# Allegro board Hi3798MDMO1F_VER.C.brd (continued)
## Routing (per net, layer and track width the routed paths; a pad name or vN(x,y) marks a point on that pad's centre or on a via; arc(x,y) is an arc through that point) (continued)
ADAC_VOUTR: length 22.4
  TOP w0.203: U1.116 79.02,62.15
  TOP w0.254: C351.1 94.08,71.48 R183.1 94,70.51 89.36,70.51 88.77,69.92 84.53,69.92 79.02,64.41 79.02,62.15
AUDIO_L: length 9.1
  BOTTOM w0.254: R72.2 105.93,77.51 105.92,77.51 C339.1 105.92,82.52 107.04,83.64 J34.2
AUDIO_R: length 10.8
  BOTTOM w0.254: J34.1 95.42,83.64 95.42,83.63 97.45,83.63 98.67,82.41 98.67,77.92 ; R74.1 98.67,76.87 98.67,77.92 ; 98.67,77.92 C140.1
CORE_CTRL: length 5.3
  TOP w0.127: R23.2 86.7,58.74 85.57,58.74 84.73,57.9 U1.106
CPU_CTRL: length 3.3
  TOP w0.127: U1.107 84.7,58.3 86.15,59.75 R21.2
CVBS: length 47.1
  TOP w0.203: U1.109 81.87,62.12
  TOP w0.254: 81.87,62.12 81.87,63.78 85,66.91 108.99,66.91 112.9,70.83 112.9,76.02 113.92,77.03 R9.1 C79.1 115.68,77.89 L6.1 116.57,77.91 C80.1
CVBS_OUT: length 13.9
  TOP w0.254: L6.2 115.71,78.71 C80.2 C17.1 121.79,78.71 v2(122.3,78.2) D9.3
  BOTTOM w0.254: J34.3 123.94,79.83 v2(122.3,78.2)
DDR_ADDR0: length 101.4
  TOP w0.127: RN2.1 v2(27.69,55.32) 26.42,55.32 20.04,48.95 20.04,31.12 32.13,19.03 65.79,19.03 77.52,30.76 77.52,33.68 77.42,33.78 U1.43
  BOTTOM w0.127: RN2.1 v2(27.69,55.32)
DDR_ADDR0_A: length 19.5
  TOP w0.127: RN2.8 30.25,55.32 32.8,57.88 42.78,57.88 44.05,56.6 44.05,54.08 43.65,53.67 U3.N3
DDR_ADDR0_B: length 24.7
  TOP w0.127: U6.N3 43.65,37.37 44.05,37.77 44.05,40.09 42.67,41.47 v1(42.67,41.52)
  BOTTOM w0.127: RN11.1 29.87,55.32 42.31,42.89 42.31,41.89 v1(42.67,41.52)
DDR_ADDR1: length 63.2
  TOP w0.127: U1.27 71.02,33.3 v1(70.62,32.9) ; RN4.4 v2(27.05,39.19)
  BOTTOM w0.127: RN4.4 v2(27.05,39.19) 25.83,37.98 25.83,32.34 32.08,26.09 64.52,26.09 70.18,31.75 70.18,32.45 v1(70.62,32.9) 70.62,32.91
DDR_ADDR1_A: length 18.7
  TOP w0.127: U3.P7 42.85,50.13 42.47,49.75 42.47,49.47 42.14,49.14 41.83,49.14 41.6,48.91 41.6,48.38 41.39,48.18 39.74,48.18 30.76,39.19 RN4.5
DDR_ADDR1_B: length 18.2
  TOP w0.127: v2(38.68,31.84) 41.25,31.84 41.61,32.2 41.61,32.48 41.81,32.68 42.19,32.68 42.49,32.99 42.49,33.34 42.85,33.69 U6.P7
  BOTTOM w0.127: v2(38.68,31.84) 38.25,32.28 36.1,32.28 33.07,35.3 33.07,35.85 29.73,39.19 RN13.4
DDR_ADDR2: length 94.9
  TOP w0.127: U1.45 v1(78.22,33.66) ; R62.1 v2(27.69,48.85)
  BOTTOM w0.127: R62.1 v2(27.69,48.85) 26.65,48.85 20.47,42.67 20.47,29.39 30.4,19.46 65.58,19.46 77.37,31.24 77.37,32.8 v1(78.22,33.66)
DDR_ADDR2_A: length 15.9
  TOP w0.127: R62.2 29.97,48.85 34.71,53.58 39.55,53.58 39.93,53.2 42.5,53.2 U3.P3
DDR_ADDR2_B: length 19.6
  TOP w0.127: v1(39.17,38.93) 39.17,38.59 39.95,37.8 39.95,37.69 40.84,36.8 42.5,36.8 U6.P3
  BOTTOM w0.127: v1(39.17,38.93) 38.86,39.24 38.86,40.29 30.3,48.85 R69.2
DDR_ADDR3: length 99.7
  TOP w0.127: RN2.2 v2(27.05,54.82) 26.54,54.82 20.47,48.75 20.47,31.32 32.33,19.46 65.58,19.46 77.02,30.9 U1.42
  BOTTOM w0.127: RN2.2 v2(27.05,54.82)
DDR_ADDR3_A: length 17.8
  TOP w0.127: U3.N2 43.65,54.57 43.25,54.97 43.25,56.75 42.55,57.44 33.01,57.44 30.38,54.82 RN2.7
DDR_ADDR3_B: length 23
  TOP w0.127: v1(41.96,41.57) 43.25,40.28 43.25,38.53 43.65,38.13 U6.N2
  BOTTOM w0.127: RN11.2 29.77,54.82 41.86,42.72 41.86,41.67 v1(41.96,41.57)
DDR_ADDR4: length 60.3
  TOP w0.127: R64.1 v2(27.69,38.18) ; U1.26 v1(70.62,33.66)
  BOTTOM w0.127: R64.1 v2(27.69,38.18) 26.65,38.18 26.26,37.8 26.26,32.54 32.28,26.52 64.31,26.52 69.75,31.96 69.75,32.78 v1(70.62,33.66)
DDR_ADDR4_A: length 19
  TOP w0.127: R64.2 30.38,38.18 39.99,47.8 42.19,47.8 42.45,48.05 42.45,48.94 42.85,49.34 U3.P8
DDR_ADDR4_B: length 18
  TOP w0.127: U6.P8 42.85,32.83 42.43,32.41 42.43,31.83 42.06,31.46 38.91,31.46 38.86,31.41 38.35,31.41 v2(37.92,31.84)
  BOTTOM w0.127: v2(37.92,31.84) 35.92,31.84 32.64,35.13 32.64,35.68 30.14,38.18 R90.2
DDR_ADDR5: length 106.9
  TOP w0.127: v1(80.22,32.9) 80.62,33.3 U1.51 ; RN2.4 v2(27.05,53.8)
  BOTTOM w0.127: v1(80.22,32.9) 79.76,32.43 79.76,31.07 66.4,17.71 29.62,17.71 18.72,28.6 18.72,45.47 v2(27.05,53.8) RN2.4
DDR_ADDR5_A: length 16.3
  TOP w0.127: U3.P2 42.45,54.75 42.45,56.05 41.94,56.56 33.34,56.56 30.58,53.8 RN2.5
DDR_ADDR5_B: length 21.6
  TOP w0.127: U6.P2 42.45,38.34 42.45,39.58 41.78,40.24 v1(41.78,40.49)
  BOTTOM w0.127: v1(41.78,40.49) 41.78,40.68 41.3,41.17 41.3,42.07 29.57,53.8 RN11.4
DDR_ADDR6: length 67.3
  TOP w0.127: RN4.2 v2(27.05,40.21) 24.89,38.05 24.89,33.91 34.92,23.88 63.58,23.88 71.42,31.72 U1.28
  BOTTOM w0.127: RN4.2 v2(27.05,40.21)
DDR_ADDR6_A: length 16.6
  TOP w0.127: U3.R8 41.76,49.55 41.34,49.13 39.47,49.13 30.56,40.21 RN4.7
DDR_ADDR6_B: length 16.3
  TOP w0.127: v2(37.77,33.14) 38.19,32.72 38.85,32.72 38.91,32.78 41.38,32.78 41.73,33.14 U6.R8
  BOTTOM w0.127: v2(37.77,33.14) 37.74,33.17 36.43,33.17 34.28,35.32 34.28,35.85 29.92,40.21 RN13.2
DDR_ADDR7: length 104.1
  TOP w0.127: R61.1 v2(27.69,52.78) ; U1.50 v1(80.22,33.66)
  BOTTOM w0.127: R61.1 v2(27.69,52.78) 26.65,52.78 19.15,45.29 19.15,28.81 29.82,18.14 66.19,18.14 79.32,31.27 79.32,32.76 v1(80.22,33.66)
DDR_ADDR7_A: length 15.5
  TOP w0.127: R61.2 30.2,52.78 33.54,56.12 41.28,56.12 41.63,55.77 41.63,54.98 42.05,54.57 U3.R2
DDR_ADDR7_B: length 20.6
  TOP w0.127: v1(41.15,40.69) 41.33,40.52 41.33,40.06 41.65,39.73 41.65,38.55 42.05,38.16 U6.R2
  BOTTOM w0.127: R68.2 29.97,52.78 40.89,41.86 40.89,40.94 41.14,40.69 v1(41.15,40.69)
DDR_ADDR8: length 69
  TOP w0.127: U1.29 71.82,33.67 71.96,33.53 71.96,31.63 63.78,23.45 34.72,23.45 24.46,33.71 24.46,38.26 26.92,40.72 v2(27.69,40.72) RN4.1
  BOTTOM w0.127: RN4.1 v2(27.69,40.72)
DDR_ADDR8_A: length 15.6
  TOP w0.127: RN4.8 30.43,40.72 39.18,49.47 41.17,49.47 U3.T8
DDR_ADDR8_B: length 15.4
  TOP w0.127: U6.T8 v2(38.58,33.14)
  BOTTOM w0.127: v2(38.58,33.14) 38.12,33.6 36.61,33.6 34.71,35.49 34.71,36.03 30.02,40.72 RN13.1
DDR_ADDR9: length 91.6
  TOP w0.127: U1.37 75.02,30.83 64.97,20.78 32.92,20.78 21.79,31.91 21.79,47.91 24.77,50.88 v2(27.05,50.88) RN1.2
  BOTTOM w0.127: RN1.2 v2(27.05,50.88)
DDR_ADDR9_A: length 14.9
  TOP w0.127: U3.R3 41.85,53.55 41.48,53.92 41.12,53.92 40.39,54.65 39.9,54.65 39.7,54.85 34.12,54.85 30.15,50.88 RN1.7
DDR_ADDR9_B: length 19.7
  TOP w0.127: U6.R3 41.85,37.14 41.45,37.54 41.09,37.54 40.54,38.09 40.54,39.08 v1(40.44,39.18)
  BOTTOM w0.127: RN9.2 30.07,50.88 40.03,40.92 40.03,39.59 v1(40.44,39.18)
DDR_ADDR10: length 54
  TOP w0.127: v1(68.62,32.9) 69.02,33.3 U1.22 ; RN6.4 v2(27.05,35.26)
  BOTTOM w0.127: v1(68.62,32.9) 68.2,32.47 68.2,31.83 63.78,27.41 32.66,27.41 27.05,33.02 v2(27.05,35.26) RN6.4
DDR_ADDR10_A: length 24
  TOP w0.127: U3.L7 45.64,49.95 45.64,48.23 43.97,46.55 41.82,46.55 30.53,35.26 RN6.5
DDR_ADDR10_B: length 22.9
  TOP w0.127: U6.L7 45.25,33.94 45.64,33.55 45.64,30.9 44.17,29.43 38.53,29.43 v2(38.3,29.2)
  BOTTOM w0.127: RN8.4 29.78,35.26 30.28,34.76 30.28,34.46 35.09,29.65 37.86,29.65 v2(38.3,29.2)
DDR_ADDR11: length 71.6
  TOP w0.127: v1(72.62,32.9) 73.02,33.3 U1.32 ; RN5.3 v2(27.69,42.5)
  BOTTOM w0.127: v1(72.62,32.9) 72.14,32.41 72.14,31.8 65.1,24.77 31.47,24.77 24.46,31.78 24.46,40.67 26.29,42.5 v2(27.69,42.5) RN5.3
DDR_ADDR11_A: length 16.2
  TOP w0.127: RN5.6 30.35,42.5 38.55,50.69 41.7,50.69 U3.R7
DDR_ADDR11_B: length 16.5
  TOP w0.127: v2(37.9,34.49) 38.1,34.28 41.7,34.28 U6.R7
  BOTTOM w0.127: RN10.3 30.05,42.5 35.94,36.6 35.94,36.11 36.69,35.36 37.02,35.36 v2(37.9,34.49)
DDR_ADDR12: length 58.4
  TOP w0.127: RN6.2 v2(27.05,36.27) 26.62,36.27 26.21,35.87 26.21,34.5 35.51,25.2 62.99,25.2 69.42,31.63 69.42,34.01 U1.23
  BOTTOM w0.127: RN6.2 v2(27.05,36.27)
DDR_ADDR12_A: length 22.1
  TOP w0.127: U3.N7 44.05,49.95 44.05,48.4 44.07,48.38 44.07,48.03 43.82,47.79 43.81,47.79 43.69,47.67 43.48,47.67 42.83,47.02 41.07,47.02 30.33,36.27 RN6.7
DDR_ADDR12_B: length 20.4
  TOP w0.127: v2(37.54,30.5) 37.97,30.07 38.53,30.07 38.84,30.37 42.42,30.37 43.38,31.34 43.76,31.34 44.04,31.62 44.04,31.63 44.05,31.63 44.05,33.29 43.65,33.69 U6.N7
  BOTTOM w0.127: v2(37.54,30.5) 35.44,30.5 35.3,30.64 35.3,30.64 32.93,33 32.93,33.01 32.69,33.25 32.68,33.25 29.66,36.27 RN8.2
DDR_ADDR13: length 97.7
  TOP w0.127: U1.46 78.62,33.3 v1(78.22,32.9) ; RN1.4 v2(27.05,49.86)
  BOTTOM w0.127: v1(78.22,32.9) 77.8,32.47 77.8,31.04 65.79,19.03 30.2,19.03 20.04,29.19 20.04,42.85 v2(27.05,49.86) RN1.4
DDR_ADDR13_A: length 13.8
  TOP w0.127: RN1.5 30.35,49.86 34.51,54.02 39.68,54.02 40.15,53.55 U3.T3
DDR_ADDR13_B: length 18.2
  TOP w0.127: v1(39.8,38.55) 40.26,38.09 40.26,37.76 40.88,37.14 U6.T3
  BOTTOM w0.127: RN9.4 29.9,49.86 39.22,40.54 39.22,39.53 39.8,38.94 v1(39.8,38.55)
DDR_ADDR14: length 70
  TOP w0.127: RN5.4 v2(27.05,41.99) ; U1.31 v1(72.62,33.66)
  BOTTOM w0.127: v1(72.62,33.66) 71.7,32.74 71.7,32.01 64.9,25.2 31.67,25.2 24.89,31.98 24.89,40.49 26.39,41.99 v2(27.05,41.99) RN5.4
DDR_ADDR14_A: length 15.4
  TOP w0.127: U3.T7 38.84,50.35 30.48,41.99 RN5.5
DDR_ADDR14_B: length 15.6
  TOP w0.127: v2(37.08,34.64) 37.08,34.54 37.66,33.96 40.85,33.96 40.88,33.94 U6.T7
  BOTTOM w0.127: v2(37.08,34.64) 36.79,34.93 36.51,34.93 35.51,35.93 35.51,36.43 29.95,41.99 RN10.4
DDR_ADDR15: length 77.5
  TOP w0.127: RN5.1 v2(27.69,43.51) ; U1.36 v1(74.62,33.66)
  BOTTOM w0.127: RN5.1 v2(27.69,43.51) 25.93,43.51 23.57,41.15 23.57,29.85 29.72,23.7 65.35,23.7 74.62,32.97 v1(74.62,33.66)
DDR_ADDR15_A: length 18.6
  TOP w0.127: RN5.8 30.15,43.51 37.8,51.16 43.63,51.16 U3.M7
DDR_ADDR15_B: length 19.4
  TOP w0.127: U6.M7 43.62,34.76 38.63,34.76 v2(37.74,35.65)
  BOTTOM w0.127: v2(37.74,35.65) 37.6,35.65 36.5,36.76 36.5,37.25 30.24,43.51 RN10.1
DDR_BA0: length 106.9
  TOP w0.127: U1.47 79.02,30.97 66.19,18.14 31.72,18.14 19.15,30.71 19.15,49.33 26.42,56.59 v2(27.05,56.59) RN7.4
  BOTTOM w0.127: RN7.4 v2(27.05,56.59)
DDR_BA0_A: length 20.2
  TOP w0.127: RN7.5 30.3,56.59 32.47,58.77 43.47,58.77 44.86,57.38 44.86,54.76 U3.M2
DDR_BA0_B: length 25.5
  TOP w0.127: U6.M2 44.84,38.33 44.84,40.7 v1(43.15,42.39)
  BOTTOM w0.127: v1(43.15,42.39) 42.88,42.66 42.88,43.51 29.79,56.59 RN14.4
DDR_BA1: length 60
  TOP w0.127: RN6.1 v2(27.69,36.78) 26.52,36.78 25.78,36.05 25.78,34.29 35.31,24.77 63.18,24.77 69.95,31.54 69.95,33.6 69.82,33.73 U1.24
  BOTTOM w0.127: RN6.1 v2(27.69,36.78)
DDR_BA1_A: length 20.3
  TOP w0.127: U3.N8 43.65,49.28 43.25,48.88 43.25,47.94 42.63,47.33 42.58,47.27 40.69,47.27 30.2,36.78 RN6.8
DDR_BA1_B: length 18.6
  TOP w0.127: v2(38.3,30.5) 38.44,30.64 42.25,30.64 43.25,31.63 43.25,32.47 43.65,32.87 U6.N8
  BOTTOM w0.127: v2(38.3,30.5) 37.82,30.98 35.57,30.98 32.86,33.69 32.86,33.69 29.76,36.78 RN8.1
DDR_BA2: length 78.4
  TOP w0.127: RN3.1 v2(27.69,46.31) 26.54,46.31 23.57,43.34 23.57,33.3 34.32,22.56 64.21,22.56 73.42,31.77 U1.33
  BOTTOM w0.127: RN3.1 v2(27.69,46.31)
DDR_BA2_A: length 18.4
  TOP w0.127: U3.M3 44.45,53 43.85,52.41 35.97,52.41 29.87,46.31 RN3.8
DDR_BA2_B: length 20.3
  TOP w0.127: U6.M3 44.45,36.72 43.79,36.06 40.16,36.06 38.56,37.66 38.56,37.74 v1(38.53,37.76)
  BOTTOM w0.127: RN12.1 30.44,46.31 37.85,38.9 37.85,38.48 38.53,37.8 v1(38.53,37.76)
DDR_CASN: length 86.5
  TOP w0.127: RN3.4 v2(27.05,44.78) ; U1.40 v1(76.22,33.66)
  BOTTOM w0.127: v1(76.22,33.66) 75.36,32.8 75.36,31.17 64.97,20.78 31.01,20.78 21.79,30 21.79,40.73 25.84,44.78 v2(27.05,44.78) RN3.4
DDR_CASN_A: length 20.8
  TOP w0.127: RN3.5 30.2,44.78 37.04,51.62 44.97,51.62 45.62,52.27 45.62,53.12 U3.K3
DDR_CASN_B: length 21.9
  TOP w0.127: U6.K3 45.67,36.76 45.67,36.26 44.7,35.3 39.47,35.3 38.35,36.42 v1(38.07,36.42)
  BOTTOM w0.127: v1(38.07,36.42) 38.07,36.45 36.96,37.57 36.96,37.99 30.16,44.78 RN12.4
DDR_CKE: length 51.8
  TOP w0.127: U1.21 v1(68.62,33.66) ; R65.1 v2(27.69,34.24)
  BOTTOM w0.127: R65.1 v2(27.69,34.24) 27.69,33.02 32.87,27.84 63.58,27.84 67.77,32.03 67.77,32.8 v1(68.62,33.66) 69.11,34.15 R38.2
DDR_CKE_A: length 23.2
  TOP w0.127: R65.2 30.15,34.24 42.2,46.3 44.25,46.3 45.71,47.76 46.05,48.1 U3.K9
DDR_CKE_B: length 21.5
  TOP w0.127: U6.K9 46.05,30.75 44.35,29.05 38.81,29.05 38.51,28.75 38,28.75 v2(37.54,29.2)
  BOTTOM w0.127: v2(37.54,29.2) 34.92,29.2 29.88,34.24 R92.2
DDR_CLK0N: length 67.3
  TOP w0.152: R35.1 65.97,29.89 62.28,26.2 36.71,26.2 34.37,28.54 34.37,37.21 42.57,45.42 47.28,45.42 v1(47.41,45.56)
  TOP w0.165: U3.K7 46.05,50.64 v1(46.53,51.12)
  BOTTOM w0.152: v1(46.53,51.12) 46.76,50.89 46.76,50.64 47.22,50.18 47.22,49.37 46.65,48.8 46.65,47.63 47.4,46.88 47.4,46.44 R11.1 47.6,45.95 47.6,45.74 v1(47.41,45.56)
DDR_CLK0P: length 67.2
  TOP w0.152: R18.1 65.75,30.11 62.15,26.51 36.83,26.51 34.67,28.67 34.67,37.09 42.7,45.12 47.67,45.12 v1(48.09,45.53)
  TOP w0.165: v1(47.19,51.12) 46.85,50.78 U3.J7
  BOTTOM w0.152: v1(47.19,51.12) 47.07,51 47.07,50.77 47.52,50.31 47.52,49.24 46.95,48.67 46.95,47.76 47.7,47.01 47.7,46.45 47.84,46.31 R15.2 47.89,45.95 47.89,45.73 v1(48.09,45.53)
DDR_CLK1N: length 62.8
  TOP w0.152: v2(47.07,43.07) 46.9,42.91 46.57,42.91 45.06,44.42 43.26,44.42 35.59,36.75 35.59,29.08 37.14,27.52 61.44,27.52 63.17,29.26 R37.1
  TOP w0.165: v1(46.29,34.92) 46.05,34.68 U6.K7
  BOTTOM w0.152: v2(47.07,43.07) 47.32,42.82 47.32,42.41 46.43,41.52 46.43,37.64 45.82,37.03 45.82,35.96 R16.1 46.08,35.2 46.29,34.98 v1(46.29,34.92)
DDR_CLK1P: length 62.6
  TOP w0.152: v2(47.89,43.07) 47.75,43.07 47.28,42.6 46.44,42.6 44.93,44.11 43.38,44.11 35.89,36.62 35.89,29.2 37.26,27.83 61.32,27.83 62.96,29.47 R36.1
  TOP w0.165: U6.J7 46.85,34.68 v1(47.09,34.92)
  BOTTOM w0.152: v2(47.89,43.07) 47.62,42.81 47.62,42.28 46.74,41.4 46.74,37.51 46.13,36.9 46.13,35.98 46.58,35.53 R17.2 46.66,35.17 46.91,34.92 v1(47.09,34.92)
DDR_CSN: length 83.8
  TOP w0.127: R63.1 v2(27.69,47.45) 25.78,47.45 22.68,44.35 22.68,32.29 33.3,21.67 64.59,21.67 73.99,31.07 73.99,33.12 73.82,33.29 U1.34
  BOTTOM w0.127: R63.1 v2(27.69,47.45)
DDR_CSN_A: length 19.2
  TOP w0.127: R63.2 29.79,47.45 35.08,52.74 43.63,52.74 44.02,53.12 44.02,53.61 44.37,53.97 44.63,53.97 45.01,54.35 U3.L2
DDR_CSN_B: length 22.3
  TOP w0.127: v1(39.29,37.53) 39.29,37.36 40.31,36.34 43.53,36.34 44.04,36.85 44.04,37.36 44.17,37.48 44.58,37.48 45.03,37.94 U6.L2
  BOTTOM w0.127: v1(39.29,37.53) 39.29,37.9 38.35,38.84 38.35,39.59 30.49,47.45 R80.2
DDR_DM0: length 9.8
  TOP w0.127: U1.181 56.1,51.5 v1(56.08,51.51) ; U3.E7 v1(50.45,50.75)
  BOTTOM w0.127: v1(50.45,50.75) 50.45,51.36 51.16,52.07 51.84,52.07 52.4,51.51 v1(56.08,51.51)
DDR_DM1: length 9.2
  TOP w0.127: U3.D3 51.08,53.55 51.54,53.09 v1(52.04,53.09) ; U1.182 56.86,51.1 56.85,51.08 v1(56.82,51.08)
  BOTTOM w0.127: v1(52.04,53.09) 52.76,52.38 56.34,52.38 56.82,51.89 v1(56.82,51.08)
DDR_DM2: length 10.4
  TOP w0.127: U6.E7 v2(50.05,34.49) ; U1.215 57.22,37.9 v1(56.77,37.45)
  BOTTOM w0.127: v1(56.77,37.45) 55.63,36.31 51.88,36.31 v2(50.05,34.49)
DDR_DM3: length 8.5
  TOP w0.127: U6.D3 51.25,36.74 v1(52.05,36.74) ; U1.216 v1(57.43,37.45)
  BOTTOM w0.127: v1(52.05,36.74) 55.33,36.74 56.52,37.92 56.95,37.92 v1(57.43,37.45)
DDR_DQ0: length 11.5
  TOP w0.127: U3.E3 v1(49.65,53.95) ; U1.167 v1(56.36,57.1)
  BOTTOM w0.127: v1(56.36,57.1) 56.03,56.77 51.22,56.77 50.45,56 50.45,55.04 49.65,54.24 v1(49.65,53.95)
DDR_DQ1: length 12
  TOP w0.127: U3.F7 49.25,50.14 49.64,49.74 49.64,47.72 50.16,47.2 53.54,47.2 53.85,47.5 U1.191
DDR_DQ2: length 11.8
  TOP w0.127: U1.164 51.73,58.3 49.65,56.22 49.65,54.75 U3.F2
DDR_DQ3: length 12
  TOP w0.127: U1.192 54.01,47.1 53.72,46.81 49.98,46.81 49.06,47.74 49.05,47.74 48.81,47.97 48.81,49.12 U3.F8
DDR_DQ4: length 13.1
  TOP w0.127: v1(48.85,53.95) 48.05,53.95 U3.H3 ; U1.166 v1(56.92,57.5)
  BOTTOM w0.127: v1(48.85,53.95) 50.06,55.16 50.06,56.18 51.04,57.15 55.68,57.15 56.08,57.56 56.86,57.56 v1(56.92,57.5)
DDR_DQ5: length 14.4
  TOP w0.127: U3.H8 47.22,49.12 47.22,47.92 47.7,47.44 47.7,47.44 49.77,45.37 54.05,45.37 54.58,45.9 U1.195
DDR_DQ6: length 12.6
  TOP w0.127: U3.G2 48.84,54.75 48.84,56 51.59,58.75 U1.163
DDR_DQ7: length 14.4
  TOP w0.127: U1.194 54.45,46.3 53.89,45.75 49.93,45.75 48.05,47.62 48.05,49.79 47.65,50.2 U3.H7
DDR_DQ8: length 8
  TOP w0.127: U1.184 v1(56.94,50.3) ; v1(51.25,50.75) U3.D7
  BOTTOM w0.127: v1(51.25,50.75) 51.67,50.32 56.92,50.32 v1(56.94,50.3)
DDR_DQ9: length 9.7
  TOP w0.127: U3.C3 52.05,53.95 52.05,56.11 52.54,56.59 54.74,56.59 55.43,55.9 U1.170
DDR_DQ10: length 8.1
  TOP w0.127: U3.C8 v1(51.25,49.15) ; U1.185 v1(56.36,49.9)
  BOTTOM w0.127: v1(56.36,49.9) 52,49.9 v1(51.25,49.15)
DDR_DQ11: length 9.8
  TOP w0.127: U1.169 55.67,56.3 54.99,56.97 52.21,56.97 51.25,56.02 51.25,54.74 U3.C2
DDR_DQ12: length 5.9
  TOP w0.127: U3.A7 54.24,50.35 55.89,48.7 U1.188
DDR_DQ13: length 5.6
  TOP w0.127: U3.A2 53.89,54.35 54.64,55.1 U1.172
DDR_DQ14: length 6.9
  TOP w0.127: U1.189 55.75,48.3 54.12,49.93 53.01,49.93 52.63,49.55 U3.B8
DDR_DQ15: length 5.7
  TOP w0.127: U3.A3 53.65,53.95 54.05,53.95 54.8,54.7 U1.173
DDR_DQ16: length 13.1
  TOP w0.127: v1(56.93,43.5) U1.201 ; U6.E3 v1(49.65,37.54)
  BOTTOM w0.127: v1(56.93,43.5) 56.89,43.46 53.45,43.46 50.85,40.86 50.85,38.99 49.65,37.78 v1(49.65,37.54)
DDR_DQ17: length 20
  TOP w0.127: U6.F7 49.25,33.68 49.64,33.28 49.64,31.34 50.6,30.38 60.1,30.38 63.42,33.7 U1.8
DDR_DQ18: length 12.8
  TOP w0.127: U6.F2 49.65,38.34 49.65,39.63 53.48,43.46 54.31,43.46 55.54,44.7 U1.198
DDR_DQ19: length 20.7
  TOP w0.127: U6.F8 48.85,32.75 48.85,31.51 50.36,30 60.26,30 63.82,33.56 U1.9
DDR_DQ20: length 14.8
  TOP w0.127: U6.H3 48.05,37.54 v1(48.85,37.54) ; v1(56.39,43.9) U1.200
  BOTTOM w0.127: v1(56.39,43.9) 53.33,43.9 50.42,40.99 50.42,39.11 v1(48.85,37.54)
DDR_DQ21: length 25
  TOP w0.127: U6.H8 47.24,32.74 47.24,30.98 49.49,28.73 60.49,28.73 65.02,33.26 U1.12
DDR_DQ22: length 13.7
  TOP w0.127: U1.197 55.4,45.1 54.2,43.89 53.34,43.89 49.1,39.66 49.08,39.66 48.85,39.43 48.85,39.4 48.84,39.4 48.84,38.34 U6.G2
DDR_DQ23: length 24.4
  TOP w0.127: U1.11 64.62,33.4 60.33,29.11 49.65,29.11 48.05,30.71 48.05,33.53 U6.H7
DDR_DQ24: length 16.6
  TOP w0.127: U6.D7 50.85,33.73 51.25,33.32 51.25,31.55 51.54,31.27 60.03,31.27 62.62,33.86 U1.6
DDR_DQ25: length 10.3
  TOP w0.127: U1.204 54.58,42.3 52.05,39.78 52.05,37.55 U6.C3
DDR_DQ26: length 13.9
  TOP w0.127: U6.C8 51.65,32.87 52.04,32.48 52.04,32.11 52.43,31.73 59.95,31.73 62.22,34 U1.5
DDR_DQ27: length 10.4
  TOP w0.127: U6.C2 51.25,38.34 51.25,39.57 54.37,42.7 U1.203
DDR_DQ28: length 8.8
  TOP w0.127: U1.2 61.02,34.63 60.33,33.94 U6.A7
DDR_DQ29: length 7.8
  TOP w0.127: U1.206 55.59,41.5 54.06,39.97 54.06,38.11 53.9,37.94 U6.A2
DDR_DQ30: length 10.4
  TOP w0.127: U6.B8 52.65,33.14 53.05,33.54 60.47,33.54 61.42,34.49 U1.3
DDR_DQ31: length 8
  TOP w0.127: U6.A3 53.65,37.54 54.05,37.54 54.44,37.94 54.44,39.79 55.75,41.1 U1.207
DDR_DQS0N: length 11.6
  TOP w0.152: U1.176 57.59,53.5 57.58,53.51 55.34,53.51 53.87,52.05 49.42,52.05 48.46,53.01 48.46,53.54 U3.G3
DDR_DQS0P: length 11.5
  TOP w0.152: U1.175 57.67,53.9 57.58,53.82 55.21,53.82 53.75,52.35 49.55,52.35 48.76,53.14 48.76,53.35 48.96,53.55 U3.F3
DDR_DQS1N: length 8.1
  TOP w0.152: U3.B7 52.4,50.31 52.16,50.31 51.99,50.47 51.99,50.85 52.32,51.18 54.71,51.18 55.87,52.34 57.81,52.34 57.85,52.3 U1.179
DDR_DQS1P: length 8.2
  TOP w0.152: U3.C7 51.69,50.39 51.69,50.98 52.2,51.49 54.58,51.49 55.74,52.65 57.74,52.65 57.79,52.7 U1.178
DDR_DQS2N: length 13.7
  TOP w0.152: U1.210 57.85,39.9 57.83,39.93 57.59,39.93 57.57,39.95 57.43,39.96 56.29,39.96 55.27,38.94 55.27,37.41 53.56,35.7 49.34,35.7 48.49,36.55 48.49,36.59 48.48,36.61 48.48,37.06 48.49,37.08 48.49,37.1 U6.G3
DDR_DQS2P: length 13.5
  TOP w0.152: U6.F3 48.98,37.14 48.78,36.94 48.78,36.73 48.79,36.72 48.79,36.68 49.47,36 53.44,36 54.97,37.53 54.97,39.07 56.16,40.26 57.55,40.26 57.57,40.25 57.57,40.25 57.59,40.27 57.83,40.27 57.85,40.3 U1.209
DDR_DQS3N: length 10.1
  TOP w0.152: U1.213 57.62,38.7 57.59,38.73 56.76,38.73 56.11,38.08 56.11,36.55 54.22,34.66 52.21,34.66 51.95,34.4 51.95,34.13 52.17,33.91 52.42,33.91 U6.B7
DDR_DQS3P: length 10.2
  TOP w0.152: U1.212 57.65,39.1 57.58,39.03 56.63,39.03 55.8,38.2 55.8,36.68 54.09,34.97 52.09,34.97 51.65,34.53 U6.C7
DDR_ODT: length 108.5
  TOP w0.127: U1.48 79.42,33.73 79.53,33.63 79.53,30.84 66.4,17.71 31.52,17.71 18.72,30.51 18.72,49.53 26.29,57.1 v2(27.69,57.1) RN7.3
  BOTTOM w0.127: RN7.3 v2(27.69,57.1)
DDR_ODT_A: length 20.2
  TOP w0.127: U3.K1 45.19,56.01 45.19,57.68 43.67,59.2 32.27,59.2 30.18,57.1 RN7.6
DDR_ODT_B: length 25.6
  TOP w0.127: U6.K1 45.19,39.6 45.19,41.12 v1(43.87,42.44)
  BOTTOM w0.127: v1(43.87,42.44) 43.84,42.44 43.31,42.97 43.31,43.69 29.9,57.1 RN14.3
DDR_PLL: length 26.4
  TOP w0.203: U1.20 68.22,36.19 67.97,36.44 v2(67.97,36.47) ; v2(59.58,48.69) 59.58,48.79 59.27,49.1 U1.187
  TOP w0.381: v2(61.52,48.69) 61.52,38.78 62.13,38.16 v2(67.97,38.16)
  BOTTOM w0.305: C270.1 v2(67.97,36.47)
  BOTTOM w0.381: v2(61.52,48.69) v2(59.58,48.69) 59.47,48.58 C264.1 ; v2(67.97,36.47) v2(67.97,38.16) C11.1 LB7.1
DDR_RASN: length 113.2
  TOP w0.127: RN7.1 v2(27.69,58.12) 26.04,58.12 17.83,49.91 17.83,30.13 31.14,16.82 66.78,16.82 81.02,31.06 U1.52
  BOTTOM w0.127: RN7.1 v2(27.69,58.12)
DDR_RASN_A: length 23.2
  TOP w0.127: U3.J3 46.85,53.81 46.46,54.2 46.46,57.73 44.1,60.09 31.94,60.09 29.97,58.12 RN7.8
DDR_RASN_B: length 29
  TOP w0.127: U6.J3 46.85,37.45 46.43,37.86 46.43,41.39 44.47,43.35 v1(43.97,43.35)
  BOTTOM w0.127: v1(43.97,43.35) 43.84,43.48 43.84,44.39 30.11,58.12 RN14.1
DDR_RESETN: length 93.3
  TOP w0.127: RN1.1 v2(27.69,51.39) 24.64,51.39 21.36,48.11 21.36,31.7 32.72,20.35 65.18,20.35 75.56,30.74 75.56,33.61 75.42,33.75 U1.38
  BOTTOM w0.127: RN1.1 v2(27.69,51.39)
DDR_RESETN_A: length 15.5
  TOP w0.127: U3.T2 40.53,55.06 v1(40.06,55.06) 39.83,55.29 33.92,55.29 30.02,51.39 RN1.8
  BOTTOM w0.127: R60.2 40.26,54.86 v1(40.06,55.06) 40,55.11 C313.1
DDR_RESETN_B: length 21.6
  TOP w0.127: U6.T2 40.86,38.33 40.86,39.33 40.85,39.34 40.85,39.61 v1(40.61,39.85)
  BOTTOM w0.127: RN9.1 30.18,51.39 40.39,41.18 40.39,40.07 v1(40.61,39.85) 40.86,39.6 40.86,38.87 40.69,38.7 C314.1 41.3,38.27 R76.2
DDR_VREF_CA_A: length 4.6
  TOP w0.305: v1(44.85,49.15) U3.M8
  BOTTOM w0.381: R51.2 C207.2 43.74,50.59 R55.1 43.74,50.21 44.22,49.73 C289.1 44.39,49.15 v1(44.85,49.15)
DDR_VREF_CA_B: length 5
  TOP w0.203: v1(44.85,31.84) 44.85,32.74 U6.M8
  BOTTOM w0.381: v1(44.85,31.84) 45.06,31.63 C310.1 R107.1 45.42,30.35 R103.2 C222.2
DDR_VREF_DQ_A: length 4.4
  TOP w0.305: v1(47.68,55.92) 47.65,55.89 U3.H1
  BOTTOM w0.381: v1(47.68,55.92) 47.68,56.76 C271.1 R75.1 R54.2 C208.2
DDR_VREF_DQ_B: length 4.6
  TOP w0.305: v1(47.65,39.8) 47.65,39.8 U6.H1
  BOTTOM w0.381: R84.1 R78.2 C223.2 48.56,40.48 C308.1 47.65,40.48 47.65,39.83 47.65,39.83 v1(47.65,39.8)
DDR_WEN: length 88.1
  TOP w0.127: v1(76.22,32.9) 76.62,33.3 U1.41 ; RN3.3 v2(27.69,45.29)
  BOTTOM w0.127: RN3.3 v2(27.69,45.29) 25.53,45.29 21.36,41.13 21.36,29.8 30.81,20.35 65.18,20.35 75.79,30.97 75.79,32.47 v1(76.22,32.9)
DDR_WEN_A: length 19.9
  TOP w0.127: U3.L3 45.25,52.48 44.71,51.95 36.73,51.95 30.07,45.29 RN3.6
DDR_WEN_B: length 21.3
  TOP w0.127: U6.L3 45.25,36.37 44.45,35.58 39.7,35.58 38.14,37.14 v1(37.97,37.14)
  BOTTOM w0.127: v1(37.97,37.14) 37.97,37.19 37.39,37.77 37.39,38.17 30.26,45.29 RN12.3
FE_1V1: length 1.9
  TOP w0.203: v1(66.9,59.76) 66.9,59.77 66.62,60.04 U1.147
  BOTTOM w0.381: C248.1 66.9,60.3 v1(66.9,59.76)
FE_3V3: length 2.1
  TOP w0.203: U1.148 v1(66.22,59.74) ; U1.144 v1(67.82,59.74)
HDMI_TX0N: length 66.8
  TOP w0.152: J26.9 30.07,82.59 29.99,82.51 29.99,81.71 30.18,81.52 U24.9 ; U24.2 30.18,79.83 30.07,79.72 30.07,74.85 32.61,72.31 38.12,72.31 45.03,65.4 57.1,65.4 61.62,69.92 69.9,69.92 74.57,65.25 74.57,62.22 74.93,61.87 74.93,61.72 75.02,61.63 U1.126
  TOP w0.165: U24.2 U24.9
HDMI_TX0P: length 66.9
  TOP w0.152: J26.7 29.07,84.64 29.07,82.83 29.68,82.22 U24.10 ; U1.127 74.62,61.74 74.27,62.1 74.27,65.12 69.77,69.61 61.75,69.61 57.23,65.09 44.91,65.09 38,72 32.49,72 29.77,74.72 29.77,79.75 29.68,79.83 U24.1
  TOP w0.165: U24.1 U24.10
HDMI_TX1N: length 67.2
  TOP w0.152: U1.130 73.42,61.48 73.36,61.54 73.36,64.71 69.39,68.68 62.08,68.68 57.58,64.17 44.56,64.17 37.64,71.09 31.47,71.09 28.4,74.16 28.4,79.65 28.51,79.76 U23.5 ; J26.6 28.57,82.69 28.37,82.49 28.37,81.65 28.51,81.52 U23.6
  TOP w0.165: U23.5 U23.6
HDMI_TX1P: length 67.3
  TOP w0.152: J26.4 27.57,82.81 28.09,82.29 28.09,81.65 28.01,81.57 U23.7 ; U1.131 73.02,61.48 73.05,61.51 73.05,64.58 69.26,68.38 62.21,68.38 57.7,63.87 44.43,63.87 37.52,70.78 31.34,70.78 28.09,74.03 28.09,79.67 28.01,79.76 U23.4
  TOP w0.165: U23.4 U23.7
HDMI_TX2N: length 67.7
  TOP w0.152: U1.132 72.62,61.53 72.59,61.57 72.59,62.89 72.01,63.47 72.01,64.31 68.86,67.46 62.61,67.46 58.09,62.93 44.04,62.93 37.13,69.84 30.68,69.84 26.92,73.6 26.92,79.69 27.01,79.78 U23.2 ; U23.9 27.01,81.49 26.81,81.69 26.81,82.41 27.07,82.66 J26.3
  TOP w0.165: U23.2 U23.9
HDMI_TX2P: length 67.7
  TOP w0.152: U23.10 26.51,82.37 26.07,82.81 J26.1 ; U1.133 72.22,61.53 72.28,61.59 72.28,62.76 71.7,63.34 71.7,64.18 68.73,67.15 62.74,67.15 58.22,62.63 43.92,62.63 37.01,69.54 30.56,69.54 26.62,73.48 26.62,79.67 26.51,79.78 U23.1
  TOP w0.165: U23.1 U23.10
HDMI_TX_1V1: length 1.8
  TOP w0.203: v1(75.09,59.74) 74.53,59.74 74.22,60.04 U1.128
HDMI_TX_3V3: length 1.1
  TOP w0.203: U1.129 v1(73.82,59.74)
HDMI_TX_CEC: length 65.2
  TOP w0.127: v2(62.31,72.18) 62.38,72.18 62.53,72.03 70.79,72.03 76.73,66.09 76.73,62.09 76.22,61.58 U1.123 ; v2(45.08,68.91) 44.57,68.91 39.09,74.39 38.76,74.39 38.63,74.52 36.37,74.52 36.02,74.87 36.02,75.33 36.42,75.72 R268.2 36.42,76.3 U4.3 34.86,77.63 32.84,79.65 32.84,82.57 32.07,83.34 J26.13
  BOTTOM w0.127: v2(45.08,68.91) 45.47,69.29 56.45,69.29 57.98,70.82 59.69,70.82 61.05,72.18 v2(62.31,72.18)
HDMI_TX_HOTPLUG: length 69.8
  TOP w0.127: v2(44.07,71.07) 43.73,71.07 39.53,75.27 C149.1 R8.2 39.03,76.41 38.92,76.53 U4.4 42.01,77.63 42.36,77.98 42.36,81.69 41.33,82.72 35.69,82.72 35.07,83.34 J26.19 ; U1.119 77.82,61.6 77.49,61.93 77.49,66.4 71.08,72.81 63.53,72.81 62.74,73.6 v2(61.72,73.6)
  BOTTOM w0.127: v2(44.07,71.07) 44.45,71.07 45.47,70.06 56.13,70.06 57.66,71.58 59.18,71.58 61.2,73.6 v2(61.72,73.6)
HDMI_TX_SCL: length 63.6
  TOP w0.127: J26.15 33.07,82.94 33.2,82.81 33.2,82.21 34.57,80.84 R186.1 36.42,80.35 36.42,80.34 U4.1 37.29,79.53 37.52,79.3 37.52,76.68 38.68,75.51 38.68,74.95 38.99,74.64 39.22,74.64 44.31,69.55 v2(44.58,69.55) ; U1.122 76.62,61.53 76.98,61.89 76.98,66.19 70.87,72.31 63.02,72.31 62.69,72.64 v2(61.65,72.64)
  BOTTOM w0.127: v2(61.65,72.64) 61.13,72.64 59.56,71.07 57.87,71.07 56.35,69.55 v2(44.58,69.55)
HDMI_TX_SDA: length 69.4
  TOP w0.127: U1.121 77.02,61.52 77.24,61.74 77.24,66.3 70.98,72.56 63.27,72.56 62.74,73.09 v2(62.36,73.09) ; v2(44.2,70.31) 44.06,70.31 39.47,74.9 39.14,74.9 38.94,75.1 38.94,75.76 37.87,76.83 37.87,79.36 38.04,79.53 U4.6 39.79,79.53 40,79.74 40,80.51 40.31,80.82 R187.1 40.84,81.31 40.7,81.45 34.67,81.45 33.57,82.55 J26.16
  BOTTOM w0.127: v2(44.2,70.31) 44.7,70.31 45.21,69.8 56.24,69.8 57.76,71.33 59.44,71.33 61.2,73.09 v2(62.36,73.09)
HDMI_TXCN: length 66.1
  TOP w0.152: U1.124 75.82,61.58 75.77,61.63 75.77,65.75 70.41,71.11 61.09,71.11 56.62,66.64 45.52,66.64 38.63,73.53 33.73,73.53 31.57,75.68 31.57,79.67 31.68,79.78 U24.5 ; J26.12 31.57,82.74 31.49,82.66 31.49,81.76 31.68,81.57 U24.6
  TOP w0.165: U24.5 U24.6
HDMI_TXCP: length 66.2
  TOP w0.152: U1.125 75.42,61.58 75.46,61.62 75.46,65.63 70.28,70.81 61.21,70.81 56.74,66.34 45.39,66.34 38.51,73.22 33.6,73.22 31.27,75.56 31.27,79.65 31.18,79.73 U24.4 ; U24.7 31.18,82.25 30.57,82.86 J26.10
  TOP w0.165: U24.4 U24.7
IR_IN: length 65.9
  TOP w0.127: J3.3 121.88,16.17 123.06,17.35 123.57,17.35 123.93,17.71 R140.1 123.51,18.3 121.93,19.88 121.93,22.16 120.65,23.45 v1(117.86,23.45) ; v2(109.35,23.45) 109.35,23.39 106.31,20.35 97.65,20.35 92.43,25.57 92.43,35 91.6,35.83 86.8,35.83 85.85,36.78 85.85,38.12 85.27,38.7 U1.58
  TOP w0.254: D3.1 122.54,13.76 121.88,14.42 J3.3
  BOTTOM w0.127: v1(117.86,23.45) v2(109.35,23.45)
LED0_BASE: length 36.7
  TOP w0.127: v1(61.23,61.91) 61.41,61.73 64.83,61.73 65.02,61.54 U1.151 ; v2(45.68,68.18) 45.68,69.46 44.7,70.44 44.7,77.03 44.56,77.18 R26.2 R67.2
  BOTTOM w0.127: v2(45.68,68.18) 45.68,65.74 51.33,60.09 59.4,60.09 61.22,61.91 v1(61.23,61.91)
LED0_LINK_ACT: length 20.6
  TOP w0.127: U1.150 65.42,61.49 64.94,61.98 61.82,61.98 61.64,62.16 61.64,62.89 63.85,65.1 v2(63.85,65.15) ; R79.2 R30.2 59.33,72.63 59.06,72.36 59.06,70.82 v2(58.29,70.06)
  BOTTOM w0.127: v2(63.85,65.15) 63.13,65.86 62.48,65.86 v2(58.29,70.06)
LED_CTRL: length 36.6
  TOP w0.127: U1.57 85.31,38.3 85.6,38.02 85.6,36.65 86.67,35.58 91.49,35.58 92.15,34.92 92.15,25.44 97.69,19.91 v2(103.17,19.91)
  BOTTOM w0.127: v2(103.17,19.91) R77.1 R3.1 R31.2
LED_GREEN: length 9.1
  TOP w0.254: R34.2 117.51,19.03 Q2.3 117.84,14.77 J3.1 117.88,14.42 118.36,13.94 118.83,13.94 119.87,12.9 LED1.3
LED_RED: length 36.3
  TOP w0.254: LED1.1 114.79,12.37 115.91,11.24 121.28,11.24 ; R22.1 122.58,17.76 120.9,16.08 120.9,13.66 121.28,13.28 121.28,11.24 ; J3.5 126.32,14.29 126.32,11.96 125.6,11.24 121.28,11.24
  BOTTOM w0.254: Q1.3 107.14,20.88 R2.2 109.43,20.13 112.05,17.51 112.05,15.25 LED1.1
NF_ALE_EMMC_PWREN: length 19.7
  TOP w0.127: U1.80 84.9,47.5 85.04,47.36 91.03,47.36 92.66,48.99 101.42,48.99 101.76,48.65 U19.17
NF_CLE: length 20.3
  TOP w0.127: U19.16 102.26,48.66 101.59,49.33 92.5,49.33 90.89,47.72 85.09,47.72 84.91,47.9 U1.81
NF_CSN0_EMMC_CMD: length 35.8
  TOP w0.127: U1.82 84.89,48.3 85.16,48.03 90.74,48.03 92.34,49.63 104.61,49.63 105.76,48.49 U19.9 105.76,46.78 105.51,46.53 v2(105.51,46.51)
  TOP w0.254: U22.W5 105.26,39.91 104.97,39.62 v1(104.95,39.62)
  BOTTOM w0.127: 103.6,41.42 103.6,39.64 104.05,39.19 104.51,39.19 v1(104.95,39.62) ; 103.6,41.42 103.6,42.04 105.16,43.6 105.16,46.16 v2(105.51,46.51) ; 103.6,41.42 103.58,41.4 R212.2
NF_DQ0_EMMC_D0: length 49.3
  TOP w0.127: U22.H3 106.26,34.33 106.67,33.91 v2(106.67,33.71) ; v2(102.71,31.7) 102.13,31.7 100.26,29.83 U19.29 100.26,27.25 99.7,26.69 98.98,26.69 R189.2 97.4,26.64 97.4,29.66 97.97,30.23 97.97,43.6 95.4,46.17 86.21,46.17 86.08,46.3 U1.77
  BOTTOM w0.127: v2(102.71,31.7) 102.71,32.42 103.52,33.24 103.52,33.82 104.25,34.55 105.83,34.55 v2(106.67,33.71)
NF_DQ1_EMMC_D1: length 50.6
  TOP w0.127: U1.76 95.29,45.9 97.71,43.47 97.71,30.48 97.12,29.89 97.12,24.85 97.56,24.4 98.5,24.4 98.81,24.71 98.81,25.6 99.09,25.88 R12.2 100.76,27.19 U19.30 100.76,29.57 101.99,30.8 v2(102.74,30.8) ; v2(105.78,33.71) 105.76,33.73 U22.H4
  BOTTOM w0.127: v2(105.78,33.71) 105.32,34.17 104.38,34.17 103.87,33.66 103.87,33.13 103.25,32.5 103.25,31.31 v2(102.74,30.8)
NF_DQ2_EMMC_D2: length 50.4
  TOP w0.127: U1.75 85.01,45.5 85.15,45.64 95.18,45.64 97.46,43.35 97.46,30.74 96.86,30.14 96.86,24.57 97.42,24.01 99.76,24.01 100.08,24.33 100.08,25.6 100.36,25.88 R29.2 101.26,26.42 U19.31 101.26,29.43 102.12,30.29 103.17,30.29 v2(103.68,30.8) ; U22.H5 105.26,34.32 104.92,33.99 v2(104.92,33.68)
  BOTTOM w0.127: v2(103.68,30.8) 103.68,32.44 104.25,33.01 v2(104.92,33.68)
NF_DQ3_EMMC_D3: length 54.2
  TOP w0.089: 106.5,34.48 106.5,34.89 U22.J2
  TOP w0.127: U1.73 84.74,44.7 85.42,45.38 95.07,45.38 97.21,43.25 97.21,30.99 96.61,30.39 96.61,24.34 97.33,23.61 100.63,23.61 101.35,24.33 101.35,25.72 101.5,25.88 R58.2 101.99,25.89 101.99,26.62 101.76,26.86 U19.32 101.76,29.3 102.25,29.79 103.38,29.79 104.27,30.68 104.27,31.18 104.62,31.54 105.64,31.54 107.11,33.01 107.11,33.88 106.5,34.48
NF_DQ4_EMMC_D4: length 53.4
  TOP w0.089: 106,34.29 106,34.89 U22.J3
  TOP w0.127: v2(105.78,32.45) 105.78,32.44 106.22,32.87 106.22,33.96 106,34.17 106,34.29 ; v2(105.63,30.55) 106.26,29.92 U19.41 106.26,27.08 105.56,26.38 104.66,26.38 R176.2 103.78,25.88 103.63,25.72 103.63,24.35 102.51,23.23 97.1,23.23 95.75,24.58 95.75,43.36 94.64,44.47 84.99,44.47 84.82,44.3 U1.72
  BOTTOM w0.127: v2(105.78,32.45) 105.78,30.7 v2(105.63,30.55)
NF_DQ5_EMMC_D5: length 55.8
  TOP w0.089: U22.J4 105.5,34.89 105.5,34.34
  TOP w0.127: v2(106.52,30.55) 106.76,30.31 U19.42 106.76,27.07 105.56,25.88 R177.2 105.05,25.88 104.78,25.6 104.78,24.28 103.35,22.85 96.98,22.85 95.49,24.34 95.49,43.24 94.51,44.21 85.17,44.21 84.85,43.9 U1.71 ; 105.5,34.34 105.5,34.11 105.35,33.96 105.35,33.29 v2(104.9,32.83)
  BOTTOM w0.127: v2(106.52,30.55) 106.3,30.77 106.3,32.96 106.05,33.22 105.28,33.22 v2(104.9,32.83)
NF_DQ6_EMMC_D6: length 57.3
  TOP w0.089: U22.J5 105,34.89 105,34.47
  TOP w0.127: v2(104.89,32.01) 104.44,32.46 104.44,33.91 105,34.47 ; U1.70 84.86,43.5 85.32,43.96 94.39,43.96 95.24,43.11 95.24,24.14 96.88,22.5 104.22,22.5 106.05,24.33 106.05,25.6 106.32,25.88 R188.2 107.26,26.44 U19.43 v2(107.26,30.17)
  BOTTOM w0.127: v2(104.89,32.01) 104.89,30.59 105.38,30.1 107.19,30.1 v2(107.26,30.17)
NF_DQ7_EMMC_D7_BOOT_SEL0: length 59.9
  TOP w0.089: U22.J6 104.51,34.9 104.51,34.49 104.37,34.34
  TOP w0.127: v2(107.76,29.53) U19.44 107.76,26.91 107.96,26.7 R202.2 107.59,25.88 107.31,25.6 107.31,24.45 106.68,23.82 106.3,23.82 104.62,22.14 96.75,22.14 94.98,23.91 94.98,42.98 94.25,43.71 85.5,43.71 84.89,43.1 U1.69 ; 104.37,34.34 103.91,33.89 103.91,32.18 v2(104.13,31.97)
  BOTTOM w0.127: v2(104.13,31.97) 104.39,31.7 104.39,30.6 105.27,29.72 107.57,29.72 v2(107.76,29.53) 107.76,29.53 R33.1
NF_RDY0_EMMC_RST: length 40.4
  TOP w0.127: U1.85 84.66,49.5 85.04,49.88 90.09,49.88 91.63,51.41 105.5,51.41 106.76,50.16 U19.7 106.76,46.63 v2(107.01,46.37)
  TOP w0.254: v1(105.78,38.91) 105.55,39.15 U22.U5
  BOTTOM w0.127: v2(107.01,46.37) 109.32,44.06 109.32,39.49 108.74,38.91 R203.2 107.44,38.81 C115.1 105.89,38.81 v1(105.78,38.91)
NF_REN_EMMC_CLK: length 31.6
  TOP w0.127: v2(106.26,46.4) U19.8 106.26,49.26 104.99,50.52 91.93,50.52 90.35,48.94 R59.1
  TOP w0.254: U22.W6 104.76,40.14 104.26,39.65 v1(104.26,39.65)
  BOTTOM w0.127: v2(106.26,46.4) 105.54,45.69 105.54,43.53 103.89,41.88 103.89,40.02 v1(104.26,39.65)
NF_WEN_EMMC_DET: length 20
  TOP w0.127: U1.79 84.97,47.1 v2(85.19,46.88) 85.39,47.08 91.26,47.08 92.89,48.71 101.11,48.71 101.26,48.57 U19.18
  BOTTOM w0.127: R56.2 85.42,47.11 v2(85.19,46.88)
NF_WP: length 3.1
  TOP w0.127: v2(100.76,46.52) U19.19
  BOTTOM w0.127: v2(100.76,46.52) R89.1 R215.2
PWR_OFF/ON: length 3.4
  TOP w0.127: U1.102 86.46,56.3 R40.1 R41.1
RECOVERY: length 57.4
  TOP w0.127: S1.2 73.18,90.09 R25.2 C138.2 73.42,88.08 v2(73.41,88.09) ; v1(83.62,60.29) 83.62,63.44 v2(83.4,63.66) ; U1.103 84.88,56.7 85.04,56.86 85.04,57.6 v1(85.55,58.11) ; v2(64.26,75.64) 65.82,74.08 71.4,74.08 v2(78.93,66.55)
  BOTTOM w0.127: v2(83.4,63.66) 80.51,66.55 v2(78.93,66.55) ; v2(73.41,88.09) 66.42,88.09 64.26,85.93 v2(64.26,75.64) ; v1(85.55,58.11) 83.62,60.04 v1(83.62,60.29)
RF0: length 8.8
  TOP w0.307: U7.3 9.34,21.24 arc(9.08,19.95) 8.35,18.85 arc(8.01,18.62) C89.1 7.59,18.54 L1.2
RF1: length 3.9
  TOP w0.307: U2.7 6.44,25.2 arc(7.18,24.09) C56.1 7.43,22.78 L7.2
RFF0: length 2.3
  TOP w0.307: L1.1 4.78,18.54 C88.1 4.77,18.54 J9.1
RFF1: length 2.2
  TOP w0.307: J8.1 4.52,22.79 C50.1 L7.1
RX+_PHY0: length 21.3
  TOP w0.152: U1.143 68.22,61.6 68.28,61.65 68.28,62.16 67.79,62.64 67.79,63.27 66.95,64.11 64.87,64.11 v2(64.65,63.9)
  BOTTOM w0.152: R97.1 52.55,65.71 52.55,64.36 53.47,63.44 U8.7 U8.2 55.12,63.44 55.22,63.54 55.62,63.54 56.18,64.11 64.44,64.11 v2(64.65,63.9)
RX-_PHY0: length 21.2
  TOP w0.152: v2(64.65,64.61) 64.84,64.42 67.08,64.42 68.1,63.4 68.1,62.77 68.58,62.28 68.58,61.65 68.62,61.61 U1.142
  BOTTOM w0.152: v2(64.65,64.61) 64.46,64.42 56.06,64.42 55.49,63.85 55.22,63.85 55.12,63.95 U8.1 U8.8 53.39,63.95 52.86,64.48 52.86,65.59 52.98,65.7 R96.1
SPDIF_OUT_BOOT_SEL1: length 2.1
  TOP w0.203: v2(78.51,61.94) 78.51,61.92 78.62,61.81 U1.117
  BOTTOM w0.254: R39.1 78.26,62.2 v2(78.51,61.94)
STANDBY_PWROFF: length 228.7
  TOP w0.127: R47.1 11.78,52.61 v2(11.43,52.27) ; v2(102.92,60.27) 103.25,60.59 R73.1 ; v2(115.16,53.84) 115.16,61.23 113.91,62.48 v2(109.17,62.48) ; LB3.2 87.39,36.38 C119.1 R88.1 91.51,36.38 92.88,35.01 v2(92.88,27.03) 92.88,25.51 97.13,21.25 v2(98.32,21.25) 105.91,21.25 117.93,33.27 117.93,49.85 v2(116.55,51.24) ; v2(16.13,47.96) 16.26,47.96 16.92,47.3 16.92,28.88 29.97,15.83 67.06,15.83 73.15,21.92 79.59,21.92 82.61,18.91 96.42,18.91 v2(96.55,18.79) ; R98.1 24.1,61.9 18.67,56.47 v2(18.67,54.82)
  BOTTOM w0.127: 16.13,52.28 v2(16.13,47.96) ; 16.13,52.28 16.12,52.27 v2(11.43,52.27) ; 16.13,52.28 v2(18.67,54.82) ; v2(116.55,51.24) 116.55,52.46 v2(115.16,53.84) ; v2(102.92,60.27) 103.37,60.71 107.4,60.71 v2(109.17,62.48) ; v2(96.55,18.79) 96.55,19.47 v2(98.32,21.25) ; R5.1 v2(92.88,27.03)
TX+_PHY0: length 21.3
  TOP w0.152: U1.146 67.02,61.45 67.01,61.47 67.01,61.95 66.07,62.89 63.47,62.89 v2(63.28,62.7)
  BOTTOM w0.152: R93.1 50.66,65.7 51.18,65.18 51.18,63.71 52.35,62.54 53.17,62.54 53.28,62.43 U8.5 U8.4 55.12,62.43 55.23,62.54 56.64,62.54 57,62.89 63.09,62.89 v2(63.28,62.7)
TX-_PHY0: length 21.3
  TOP w0.152: U1.145 67.42,61.5 67.31,61.61 67.31,62.08 66.19,63.2 63.49,63.2 v2(63.28,63.41)
  BOTTOM w0.152: v2(63.28,63.41) 63.06,63.2 56.87,63.2 56.52,62.84 55.22,62.84 55.13,62.93 U8.3 U8.6 53.28,62.93 53.19,62.84 52.48,62.84 51.49,63.83 51.49,65.31 R94.1
UART0_RXD: length 35.7
  TOP w0.127: J18.2 93,20.97 91.97,21.99 87.81,21.99 R136.1 ; v2(93.55,25.52) 93.57,25.52 93.83,25.77 93.83,35.32 91.4,37.75 88.25,37.75 86.5,39.5 U1.60
  BOTTOM w0.127: J18.2 93,23.65 93.71,24.36 94.3,24.36 94.59,24.66 94.59,25.24 94.31,25.52 v2(93.55,25.52)
UART0_TXD: length 32.9
  TOP w0.127: U1.61 84.79,39.9 84.92,39.77 86.62,39.77 88.37,38.02 91.52,38.02 94.09,35.44 94.09,25.05 v2(94.03,24.99) ; R135.2 88.49,21.66 91.31,21.66 91.75,21.23 J18.3
  BOTTOM w0.127: v2(94.03,24.99) 93.75,24.99 92.58,23.82 92.58,21.91 91.75,21.07 J18.3
USB0_DM: length 29
  TOP w0.203: v2(69.58,62.7) 69.39,62.5 69.39,61.63 69.42,61.59 U1.140 ; J12.2 69.31,81.78 70.84,81.78 72.7,79.92 73.42,79.92 D5.1 73.97,79.95 74.28,79.95 74.68,79.56 74.68,77.33 73.61,76.26 73.61,75.53 C103.1 73.61,74.97 73.61,74.65 v2(73.89,74.37)
  BOTTOM w0.203: v2(69.58,62.7) 69.39,62.89 69.39,69.24 73.61,73.46 73.61,74.08 v2(73.89,74.37)
USB0_DP: length 29.1
  TOP w0.203: v2(72.99,74.37) 73.28,74.65 73.28,74.87 72.92,75.23 C106.1 73.28,75.61 73.28,76.4 74.35,77.46 74.35,79.42 74.14,79.62 74.02,79.62 D4.1 73.43,79.59 72.56,79.59 70.7,81.45 68.94,81.45 68.66,81.18 J12.3 ; v2(68.87,62.7) 69.06,62.5 69.06,61.63 69.02,61.59 U1.141
  BOTTOM w0.203: v2(68.87,62.7) 69.06,62.89 69.06,69.38 73.28,73.6 73.28,74.08 v2(72.99,74.37)
USB01_1V1: length 1.4
  TOP w0.203: v1(71.08,59.74) 70.89,59.74 70.62,60 U1.137
USB01_3V3: length 1.5
  TOP w0.203: v1(69.22,59.74) 69.55,59.74 69.82,60.01 U1.139
USB1_DM: length 84.8
  TOP w0.203: v2(8.96,40.35) 10.86,38.45 U7.7 ; U1.135 71.42,61.59 71.35,61.66 71.35,62.18 70.84,62.69 70.84,63.71 68.34,66.21 63.14,66.21 58.39,61.46 31.32,61.46 29.45,59.59 25.64,59.59 12.99,46.94 10.03,46.94 9.32,46.23 9.32,44.82 8.87,44.37 J2.4
  BOTTOM w0.203: J2.4 8.87,42.3 9.71,41.46 9.71,40.32 9.51,40.12 9.19,40.12 v2(8.96,40.35)
USB1_DP: length 84.7
  TOP w0.203: U1.136 71.02,62.04 70.51,62.55 70.51,63.57 68.2,65.88 63.28,65.88 58.53,61.13 31.46,61.13 29.59,59.26 25.78,59.26 13.13,46.61 10.17,46.61 9.65,46.09 9.65,44.82 9.83,44.65 10.72,44.65 10.87,44.49 J2.3 ; U2.2 7.36,38.95 7.96,39.55 v2(8.96,39.55)
  BOTTOM w0.203: J2.3 10.87,42.4 10.04,41.56 10.04,40.18 9.65,39.79 9.19,39.79 v2(8.96,39.55)
USB2_DM: length 112.8
  TOP w0.203: U1.89 84.95,51.1 84.98,51.14 89.8,51.14 91.06,52.39 119.53,52.39 126.75,59.61 126.75,75.63 121.92,80.46 112.01,80.46 111.02,79.47 90.3,79.47 87.3,82.47 D7.1 85.37,82.29 84.01,82.29 83.53,81.81 81.13,81.81 J7.2
USB2_DP: length 112.8
  TOP w0.203: J7.3 80.42,80.52 80.42,81.32 80.57,81.48 83.67,81.48 84.15,81.96 85.17,81.96 D6.1 85.57,81.58 86.13,82.14 87.16,82.14 90.16,79.14 111.16,79.14 112.15,80.13 121.78,80.13 126.42,75.5 126.42,59.74 119.4,52.72 90.92,52.72 89.66,51.47 84.98,51.47 84.95,51.5 U1.90
USB03_VBUS: length 22.3
  TOP w1.143: 77.57,74.62 76,76.19 76,83 75.62,83.38 ; J7.1 79.59,84.43 78.54,83.38 75.62,83.38 ; 75.62,83.38 70.64,83.38 69.59,84.43 J12.1
  vias: v2(82.42,75.13) v2(82.42,74.36) v2(83.19,75.13) v2(83.19,74.36)
USB_BOOT: length 13.3
  TOP w0.127: R42.2 86.21,65.91 84.91,64.61 84.91,59.2 84.46,58.75 U1.108
VDAC_3V3: length 1.1
  TOP w0.203: U1.112 v1(80.62,59.74)
XIN: length 11.1
  TOP w0.203: U1.63 87.38,40.7 R1.2 89.31,39.87 C364.1 89.94,39.72 90.27,40.05 90.27,40.66 90.5,40.89 92.25,40.89 93.18,39.96 X2.1
XOUT: length 5.9
  TOP w0.203: R14.1 88.95,40.61 R1.1 87.97,41.1 U1.64
$4N588: length 3.8
  TOP w0.254: R10.1 C84.1 R52.1 5.82,54.14 U15.5
$4N593: length 3.8
  TOP w0.127: U15.1 9.12,54.7 C30.1 10.73,53.77 R6.2 11.77,53.77 R47.2
$4N676: length 24.4
  TOP w0.127: R21.1 C71.1 86.62,62.89 86.82,63.09 86.82,64.76 86.99,64.94 v2(102.51,64.94) ; v2(102.51,63.34) C43.1 R7.2
  BOTTOM w0.127: v2(102.51,63.34) v2(102.51,64.94)
$4N677: length 4.7
  TOP w0.508: U11.6 108.89,59.45 R99.2 108.88,60.79 R53.1 C76.1 R70.1
$4N687: length 3
  TOP w0.508: R73.2 C8.1 104.72,59.28 U11.1
$4N714: length 4.2
  TOP w0.508: C82.1 R101.1 R13.2 89.87,23.84 R110.1 88.61,23.84 U13.6
$4N715: length 97.2
  TOP w0.127: R23.1 C72.1 89.37,64.03 113.92,64.03 116.26,61.69 116.26,54.32 v2(116.59,53.99) ; R102.2 C45.1 93.6,22.93 97.56,18.97 106.22,18.97 119.18,31.92 119.18,49.93 v2(117.73,51.38)
  BOTTOM w0.127: v2(116.59,53.99) 117.73,52.85 v2(117.73,51.38)
$4N716: length 1
  TOP w0.127: R102.1 90.69,23.19 R110.2
$4N724: length 3.9
  TOP w0.508: U13.1 88.41,27.39 v2(88.49,27.47)
  BOTTOM w0.508: v2(88.49,27.47) 88.93,27.03 R5.2 89.88,27.03 C5.1
$4N894: length 1.4
  TOP w0.508: R7.1 104.42,61.61 R70.2
$4N901: length 4
  TOP w0.508: R105.1 15.87,63.64 16.9,63.64 R100.1 16.91,64.18 17.37,64.64 U14.5
$4N903: length 5.9
  TOP w0.254: U14.1 21.18,73.13 v2(21.19,73.14)
  BOTTOM w0.254: v2(23.24,71.44) 23.24,71.95 22.05,73.14 v2(21.19,73.14) 20.68,73.65 R95.1
$4N904: length 0.9
  TOP w0.254: C83.2 18.79,62.7 R104.1
$4N905: length 3.9
  TOP w0.254: C83.1 C24.1 17.99,64.43 18.64,65.08 U14.6
$4N906: length 2.9
  TOP w0.254: U14.7 19.91,64.74 20.44,64.21 R4.2
$4N919: length 1.8
  TOP w0.254: C44.1 21.23,66.35 U14.8
$4N923: length 0.9
  BOTTOM w0.254: R95.2 19.24,74.46 C65.1
$4N925: length 1.6
  BOTTOM w0.254: v2(17.61,73.64) 17.62,73.63 C65.2
$5N541: length 4.7
  TOP w0.254: R118.2 29.86,63.59 28.78,64.67 Q4.3 27.26,64.67 26.93,65 R144.2
$5N542: length 118.7
  TOP w0.127: v2(19.3,55.32) 19.3,56.59 23.5,60.78 29.05,60.78 30.43,62.17 R118.1 ; v2(69.98,17.6) 67.18,14.81 29.72,14.81 16,28.53 v2(16,31.7) ; v2(72.77,17.6) 72.78,17.61 Q13.1
  TOP w0.203: R118.1 30.74,62.78 31.11,63.16 31.11,67.77 30.02,68.87 Q14.1 27.45,69.55 C6.2
  BOTTOM w0.127: v2(16,31.7) 16.64,32.34 16.64,52.15 19.3,54.82 v2(19.3,55.32) ; v2(69.98,17.6) 69.98,17.61 72.76,17.61 v2(72.77,17.6)
$5N549: length 1.9
  TOP w0.127: Q4.1 26.67,62.72 R98.2
$6N188: length 3.6
  TOP w0.203: X2.3 90.96,41.55 90.6,41.55 89.71,42.44 C365.1 R14.2
$6N1407: length 1.8
  TOP w0.127: v2(65.62,61.89) 65.82,61.69 U1.149
  BOTTOM w0.127: v2(65.62,61.89) 65.61,61.88 R173.1
$6N2385: length 2.9
  TOP w0.203: U1.138 v1(70.22,59.53)
  BOTTOM w0.381: v1(70.22,59.53) 70,59.31 R82.2 R85.2
$6N2411: length 38.8
  TOP w0.127: R42.1 112.78,65.91 v2(112.82,65.86) ; C136.1 121.41,69.92 120.43,68.94 S2.2 119.27,67.78 118.63,67.13 v2(118.63,66.65) 118.63,65.31 119.21,64.73 119.21,62 119.63,61.58 S2.1
  BOTTOM w0.127: v2(112.82,65.86) 117.84,65.86 v2(118.63,66.65)
$6N2437: length 2.6
  TOP w0.127: U1.84 84.76,49.1 84.92,48.94 R59.2
$6N2445: length 4.8
  TOP w0.127: U1.59 85.85,39.1 C118.1 86.84,38.59 87.38,38.05 LB3.1
$7N1408: length 2.1
  TOP w0.203: v1(79.96,59.74) 79.97,59.74 80.22,59.99 U1.113
  BOTTOM w0.381: C250.2 79.63,60.08 79.97,59.74 v1(79.96,59.74)
$7N1763: length 2.1
  TOP w0.203: U1.111 81.02,59.99 81.28,59.74 v1(81.28,59.74)
  BOTTOM w0.381: R32.2 81.53,60 81.28,59.74 v1(81.28,59.74)
$7N2000: length 3.8
  TOP w0.203: U1.87 84.8,50.3 84.84,50.34 v1(85.23,50.34)
  TOP w0.381: v1(85.23,50.34) R87.2
  BOTTOM w0.381: v1(85.23,50.34) R87.2
$8N1506: length 2.4
  TOP w0.127: U1.54 81.87,34.15 v2(81.99,34.03)
  BOTTOM w0.127: v2(81.99,34.03) 82.07,34.1 R45.1
$8N1694: length 5.3
  TOP w0.152: R18.2 66.75,31.1 67.08,31.43 67.08,32.03 66.85,32.26 66.85,32.59 67.08,32.82 67.08,33.1 66.85,33.33 66.85,33.66 67.08,33.89 67.08,34.47 67.02,34.53 U1.17
$8N1695: length 5.1
  TOP w0.152: U1.18 67.42,34.53 67.39,34.49 67.39,31.31 66.96,30.88 R35.2
$8N1696: length 6.5
  TOP w0.152: U1.14 65.82,34.55 65.88,34.49 65.88,32.39 65.57,32.08 65.28,32.08 65.08,31.88 65.08,31.59 64.88,31.39 64.59,31.39 64.39,31.2 64.39,30.9 63.95,30.47 R36.2
$8N1697: length 6.4
  TOP w0.152: U1.15 66.22,34.52 66.18,34.48 66.18,32.26 64.17,30.25 R37.2
$9N2352: length 1.9
  TOP w0.254: U1.55 84.89,37.45 v2(85.12,37.23)
  BOTTOM w0.381: C255.2 v2(85.12,37.23)
$9N2555: length 3.4
  TOP w0.203: U1.65 84.94,41.5 v1(85.24,41.8)
  BOTTOM w0.381: v1(85.24,41.8) 85.85,42.41 C122.1 85.86,42.48 LB5.2
$10N1056: length 4.6
  BOTTOM w0.381: R15.1 49.06,45.57 48.44,44.96 47.22,44.96 46.82,45.36 C328.1 46.44,45.48 R11.2
$10N1121: length 1.3
  TOP w0.165: U3.L8 v1(44.85,49.95)
  BOTTOM w0.127: v1(44.85,49.95) 44.63,50.17 R46.2
$11N1393: length 4.1
  BOTTOM w0.203: R16.2 45.97,34.49 47.27,34.49 47.6,34.82 47.6,35.4 R17.1
  BOTTOM w0.254: C330.1 47.47,36.44 R17.1
$11N1414: length 2.5
  TOP w0.127: U6.L8 44.85,33.54 v1(44.85,34.34)
  BOTTOM w0.127: v1(44.85,34.34) 44.82,34.37 44.06,34.37 R71.2
$12N1655: length 3.3
  TOP w0.254: U19.38 104.76,27.1 104.39,26.74 103.86,26.74 R49.2
$12N1661: length 2.1
  TOP w0.127: v2(105.26,26.87) U19.39
  BOTTOM w0.127: R57.1 v2(105.26,26.87)
$12N1670: length 2.9
  TOP w0.089: v2(107.69,35.39) 107.01,35.39 U22.K2
  BOTTOM w0.203: C124.1 107.05,36.03 v2(107.69,35.39) 108.07,35.78 C123.1
$13N803: length 2.1
  TOP w0.254: v2(89.38,78.64) 89.15,78.87 U26.3
  BOTTOM w0.381: R220.1 89.59,78.43 v2(89.38,78.64)
$13N804: length 2.3
  TOP w0.381: U26.4 85.75,79.54 86.64,80.43 R106.2
$14N721: length 1.9
  TOP w0.254: Q2.1 120.66,18.23 R22.2
$14N731: length 4.4
  BOTTOM w0.254: R3.2 107.08,17.52 Q1.1
$15N1021: length 1.3
  TOP w0.254: R193.1 95.57,72.41 C351.2
$15N1022: length 3.6
  TOP w0.254: R27.2 96.09,76.37 C55.1 98.15,76.37 98.29,76.5 U5.2
$15N1025: length 3.7
  TOP w0.254: R27.1 R19.1 94.46,74.82 C317.1 94.47,73.73 R193.2
$15N1029: length 8.5
  TOP w0.254: R19.2 96.09,74.95 96.7,75.56 C55.2 97.97,75.56 98.27,75.85 U5.3 100.71,75.85 101.09,76.24 v2(101.09,76.27)
  BOTTOM w0.254: v2(101.09,76.27) 100.5,76.86 R74.2 99.45,76.84 R146.1
$15N1031: length 3.2
  TOP w0.254: U5.13 106.64,76.5 106.73,76.6 C54.2 108.25,76.6 R28.1
$15N1032: length 7.6
  TOP w0.254: R20.1 108.1,75.78 C54.1 106.41,75.78 106.34,75.85 U5.12 104.4,75.85 v2(103.79,76.46)
  BOTTOM w0.254: R145.1 105.1,76.85 R72.1 104.19,76.86 v2(103.79,76.46)
$15N1036: length 1.2
  TOP w0.254: R194.2 C350.1
$15N1037: length 3.7
  TOP w0.254: R194.1 C316.1 R28.2 R20.2
$15N1074: length 2
  TOP w0.254: R44.1 108.37,73.39 R48.2 108.36,73.39 R43.2
$15N1075: length 2.5
  TOP w0.254: U5.11 106.61,75.2 R43.1
$15N1082: length 3.4
  TOP w0.254: U5.7 101.15,73.25 C32.1
$15N1083: length 2.1
  TOP w0.254: U5.6 97.98,73.9 C33.2
$15N1085: length 2.7
  TOP w0.254: C32.2 104.54,73.25 U5.8
$15N1114: length 7
  TOP w0.254: U5.5 97.6,74.55 97.03,73.98 97.03,72.14 C363.1 98.97,71.51 R66.1
$16N1065: length 2.9
  TOP w0.508: v2(54.99,68.4) 55,68.41 T2.7
  BOTTOM w0.508: C154.1 55.12,68.53 v2(54.99,68.4) 54.86,68.53 C297.1
$16N1066: length 3.6
  TOP w0.381: J25.9 44.18,82.2 R67.1
$16N1067: length 9.5
  TOP w0.381: J25.11 59.62,78.9 R79.1
$16N1068: length 12
  BOTTOM w0.508: J25.7 53.93,88.39 J25.8 54.94,85.88 51.82,82.76 R270.2
$16N1069: length 2.5
  TOP w0.381: T2.15 v2(48.65,79.85)
  BOTTOM w0.508: R271.2 48.26,79.46 v2(48.65,79.85)
$16N1070: length 3.1
  TOP w0.381: T2.10 v2(55,79.85)
  BOTTOM w0.381: v2(55,79.85) 54.99,79.85 54.58,79.85 R269.2
$16N1072: length 12.6
  TOP w0.254: T2.9 56.26,78.54 56.26,80.16 56.06,80.36 54.41,80.36 54.11,80.66 54.11,81.42 52.27,83.25 52.27,84.63 52.78,85.14 52.78,85.65 52.27,86.16 52.27,87.32 52.43,87.47 52.82,87.47 J25.6
$16N1073: length 12.6
  TOP w0.254: T2.11 53.73,81.26 51.89,83.1 51.89,87.76 50.5,89.16 J25.3
$16N1074: length 9.3
  BOTTOM w0.508: R269.1 R270.1 R272.1 R271.1 47.03,77 46.01,78.02 C23.1
$16N1075: length 12.4
  TOP w0.254: J25.1 47.83,88.29 47.19,87.64 47.19,85.69 49.07,83.81 49.07,81.67 48.39,80.98 48.39,80.49 47.38,79.47 T2.16
$16N1076: length 12.3
  TOP w0.254: J25.2 48.85,87.62 48.51,87.95 48.04,87.95 47.57,87.49 47.57,85.85 49.45,83.97 49.45,81.51 48.77,80.83 48.77,80.46 49.91,79.32 49.91,78.54 T2.14
$16N1077: length 11.1
  BOTTOM w0.508: R272.2 50.04,84.41 50.88,85.25 J25.4 50.88,88.14 J25.5
$16N1078: length 2.9
  TOP w0.508: v2(48.64,68.4) 48.65,68.41 T2.2
  BOTTOM w0.508: C307.1 48.77,68.53 v2(48.64,68.4) 48.51,68.53 C153.1
$16N1097: length 4.3
  TOP w0.152: T2.8 56.27,68.41 v2(55.37,67.52)
  BOTTOM w0.152: v2(55.37,67.52) 55.37,67.26 R96.2
$16N1098: length 4.1
  TOP w0.152: T2.6 53.73,68.4 v2(54.61,67.52)
  BOTTOM w0.152: v2(54.61,67.52) 54.76,67.36 54.76,67.16 54.52,66.91 R97.2
$16N1099: length 4.2
  TOP w0.152: v2(49.02,67.52) 49.91,68.4 49.91,69.05 49.92,69.06 T2.3
  BOTTOM w0.152: R94.2 49.04,66.91 48.85,67.11 48.85,67.34 v2(49.02,67.52)
$16N1100: length 4.3
  TOP w0.152: T2.1 47.38,68.4 v2(48.26,67.52)
  BOTTOM w0.152: v2(48.26,67.52) 48.26,67.26 R93.2
$18N796: length 2
  TOP w0.254: D19.1 34.36,75.4 35.26,76.3 R268.1

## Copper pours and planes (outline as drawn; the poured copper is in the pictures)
1V1_CORE on TOP (solid shape): outline of 217 points within 61.37,27.35 85.98,59.84
1V1_CORE on BOTTOM (solid shape): 81.99,45.38 81.99,45.05 81.89,44.95 81.2,44.95 81,44.75 81,44.04 80.98,44.01 80.16,44.01 80.14,44.04 80.14,45.26 80.35,45.47 81.9,45.47
1V1_CORE on BOTTOM (solid shape): 77.22,59.67 77.22,59.58 78,58.79 78,58.21 77.98,58.18 77.47,58.18 77.43,58.22 77.43,58.3 77.17,58.57 76.84,58.57 76.78,58.62 77.6,58.62 77.6,58.87 77.32,58.87 77.32,58.62 76.78,58.62 76.68,58.72 76.68,59.76 76.75,59.82 77.06,59.82
